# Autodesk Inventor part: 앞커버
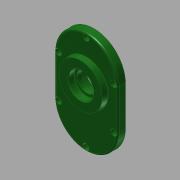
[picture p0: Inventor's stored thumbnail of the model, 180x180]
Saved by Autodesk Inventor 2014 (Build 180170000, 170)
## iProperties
Created: 2016-12
Part Number: 앞커버
Material: Aluminum 6061
Document SubType Name: Modeling
Designer: mduedu
Density: 1 g/cm^3
Appearance: Smooth - Dark Forest Green
Mass: 97.7255 g
Surface Area: 264.104 cm^2
Volume: 97.7255 cm^3
Author: mduedu
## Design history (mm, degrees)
sketch "스케치1"
  geometry: L1 (40, -25)-(40, 25); L2 (-40, 25)-(-40, -25); L3 (-40, -25)-(40, 25); L4 (40, -25)-(-40, 25); A1 r 40 centre (0, 25) between (40, 25) and (-40, 25); A2 r 40 centre (0, -25) between (-40, -25) and (40, -25); 1 further point
  constraints: 8 end point, 4 point on circle, 4 tangent, 2 centre point, 2 midpoint, 1 parallel, 1 vertical
  dimensions: "d0" = 130 dimension on A2 A1; "d2" = 80 distance between parallel lines of L1 L2
extrude "돌출1" new body sketch "스케치1" distance "d3" = 10; taper "d4" = 0 deg
sketch "스케치2"
  geometry: C1 r 21 at (0, 11); 1 further point
  constraints: 1 centre point, 1 vertical alignment
  dimensions: "d5" = 42 diameter of C1; "d7" = 11 distance of C1.centre point (0, 0)
extrude "돌출2" join sketch "스케치2" distance "d8" = 7; taper "d9" = 0 deg
sketch "스케치3"
  geometry: C1 r 15 at (0, -33.1); C2 r 21 at (0, 11) reference; 1 further point
  constraints: 1 centre point, 1 vertical alignment
  dimensions: "d10" = 30 diameter of C1; "d71" = 44.1 distance of C1.centre C2.centre
extrude "돌출3" join sketch "스케치3" distance "d12" = 7; taper "d13" = 0 deg
sketch "스케치4"
  geometry: C1 r 28 at (0, 11); A1 r 21 centre (0, 11) between (8.978, -7.984) and (-8.978, -7.984) reference; 1 further point
  constraints: 1 centre point, 1 coincident
  dimensions: "d14" = 56 diameter of C1
extrude "돌출4" join sketch "스케치4" distance "d15" = 7; taper "d16" = -5 deg
hole "구멍1" diameter "d19" = 35; stored, may be unused: countersink angle "d23" = 90 deg, drill point angle "d25" = 0 deg; dims "d17" = 10, "d18" = 10, "d20" = 6, "d21" = 4, "d22" = 2, "d24" = 10
hole "구멍2" diameter "d28" = 22; stored, may be unused: countersink angle "d32" = 90 deg, drill point angle "d34" = 0 deg; dims "d26" = 10, "d27" = 10, "d29" = 6, "d30" = 4, "d31" = 2, "d33" = 7
hole "구멍3" diameter "d37" = 19; stored, may be unused: countersink angle "d41" = 90 deg, drill point angle "d43" = 0 deg; dims "d35" = 10, "d36" = 10, "d38" = 6, "d39" = 4, "d40" = 2, "d42" = 1
hole "구멍4" diameter "d46" = 32; stored, may be unused: countersink angle "d50" = 90 deg, drill point angle "d52" = 0 deg; dims "d44" = 10, "d45" = 10, "d47" = 6, "d48" = 4, "d49" = 2, "d51" = 8
hole "구멍5" diameter "d55" = 25; stored, may be unused: countersink angle "d59" = 90 deg, drill point angle "d61" = 0 deg; dims "d53" = 10, "d54" = 10, "d56" = 6, "d57" = 4, "d58" = 2, "d60" = 8
fillet "모깎기1" dims "d62" = 0.3
fillet "모깎기2" dims "d63" = 2
chamfer "모따기1" distance "d64" = 1; stored, may be unused: second distance "d65" = 2, angle "d66" = 45 deg
fillet "모깎기4" dims "d68" = 2
fillet "모깎기5" dims "d69" = 0.3
fillet "모깎기6" dims "d70" = 2
sketch "스케치5"
  geometry: L1 (-40, 25)-(-40, -25) reference; L2 (40, -25)-(40, 25) reference; L3 (35, 25)-(35, -25); L4 (-35, -25)-(-35, 25); A1 r 40 centre (0, 25) between (40, 25) and (-40, 25) reference; A2 r 40 centre (0, -25) between (-40, -25) and (40, -25) reference; A3 r 35 centre (0, 25) between (35, 25) and (-35, 25); A4 r 35 centre (0, -25) between (-35, -25) and (35, -25); 2 further points
  constraints: 5 point on circle, 4 end point, 2 centre point, 1 vertical alignment, 3 other
  dimensions: "d72" = 5 distance between parallel lines of L2 L3
sketch "스케치7"
  geometry: 1 further point
hole "구멍7" sketch "스케치7" at (0, 60) diameter "d80" = 4.5; stored, may be unused: countersink angle "d84" = 90 deg, drill point angle "d86" = 0 deg; dims "d81" = 6, "d82" = 8, "d83" = 4.6, "d85" = 8
node "솔리드1"
pattern_linear "직사각형 패턴1"
